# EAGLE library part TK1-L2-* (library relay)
ULTRA LOW PROFILE 2 AMP. POLARIZED RELAY NAiS 2 coil latching Source: http://www.mew-europe.com/.. en_ds_61018_0000.pdf
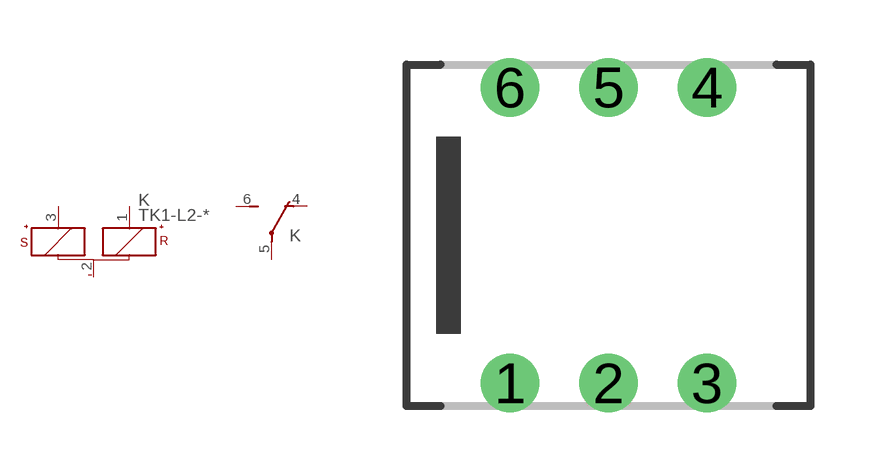
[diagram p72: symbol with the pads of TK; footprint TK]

Designator prefix K; gates -=+KS+KR- G$1=U

## TK1-L2-1.5V (OC_FARNELL: unknown; OC_NEWARK: unknown), TK1-L2-3V (MPN: TK1-L2-3V; OC_FARNELL: unknown; OC_NEWARK: 15P9753), TK1-L2-4.5V (MPN: TK1-L2-4.5V; OC_FARNELL: unknown; OC_NEWARK: 15P9754), TK1-L2-5V (MPN: TK1-L2-5V; OC_FARNELL: unknown; OC_NEWARK: 15P9755), TK1-L2-6V (OC_FARNELL: unknown; OC_NEWARK: unknown), TK1-L2-9V (OC_FARNELL: unknown; OC_NEWARK: unknown), TK1-L2-12V (MPN: TK1-L2-12V; OC_FARNELL: unknown; OC_NEWARK: 15P9751), TK1-L2-24V (MPN: TK1-L2-24V; OC_FARNELL: unknown; OC_NEWARK: 15P9752), TK1-L2-H-1.5V (OC_FARNELL: unknown; OC_NEWARK: unknown), TK1-L2-H-3V (OC_FARNELL: unknown; OC_NEWARK: unknown), TK1-L2-H-5V (OC_FARNELL: unknown; OC_NEWARK: unknown), TK1-L2-H-6V (OC_FARNELL: unknown; OC_NEWARK: unknown), TK1-L2-H-9V (OC_FARNELL: unknown; OC_NEWARK: unknown), TK1-L2-H-12V (OC_FARNELL: unknown; OC_NEWARK: unknown), TK1-L2-H-24V (OC_FARNELL: unknown; OC_NEWARK: unknown)  [TK]
1  -:R+  pas
2  -:-  pas
3  -:S+  pas
4  G$1:O  pas
5  G$1:P  pas
6  G$1:S  pas

## Footprint TK (pad centres in mm)
ULTRA LOW PROFILE 2 AMP. POLARIZED RELAY NAiS Source: http://www.mew-europe.com/.. en_ds_61018_0000.pdf
drill 1 round: 1 -2.54,-3.81; 2 0,-3.81; 3 2.54,-3.81; 4 2.54,3.81; 5 0,3.81; 6 -2.54,3.81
